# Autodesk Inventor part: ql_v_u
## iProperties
Created: 2007-11
Part Number: ql_v_u
Document SubType Name: Modeling
Designer: martin
Manufacturer: Standard
Standards Organization: Custom
Author: martin
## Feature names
1. Extrusion2
